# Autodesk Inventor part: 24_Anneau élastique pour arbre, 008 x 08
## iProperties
Created: 2001-06
Part Number: 24_Anneau élastique pour arbre, 008 x 08
Material: Par défaut
Document SubType Name: Modélisation
Designer: FIEVET
Control State: 0
Master: False
Checked Out: False
Shininess: 20.0
Length Units: 11269
Angle Units: 11279
Time Units: 11290
Mass Units: 11283
Length Display Precision: 3
Angle Display Precision: 2
Compacted: True
Density: 0.0
Volumn: 0.0
Area: 0.0
PropertySet Name: Model Information
Author: FIEVET
